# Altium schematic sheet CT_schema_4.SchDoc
size 282 x 169 mm
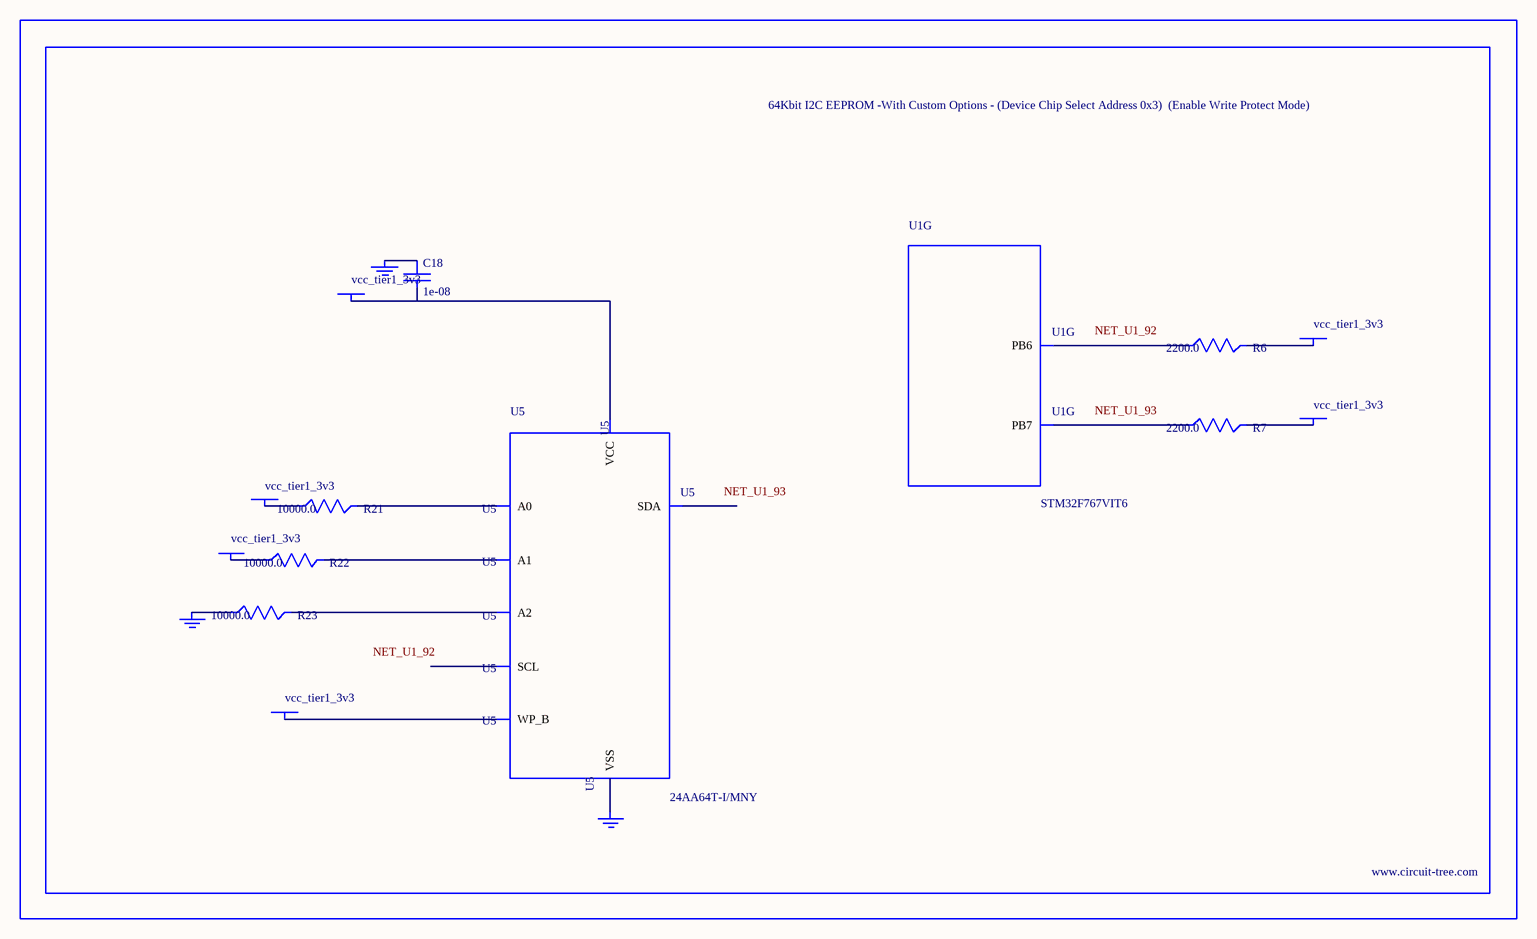
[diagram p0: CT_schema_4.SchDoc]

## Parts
BORDER3  (no value)
C18  1e-08  [C0402]
GND_INSTANCE_3_0  (no value)
GND_INSTANCE_3_1  (no value)
GND_INSTANCE_3_2  (no value)
POWER_INSTANCE_3_0  vcc_tier1_3v3
POWER_INSTANCE_3_1  vcc_tier1_3v3
POWER_INSTANCE_3_2  vcc_tier1_3v3
POWER_INSTANCE_3_3  vcc_tier1_3v3
POWER_INSTANCE_3_4  vcc_tier1_3v3
POWER_INSTANCE_3_5  vcc_tier1_3v3
R6  2200.0  [R0603]
R7  2200.0  [R0603]
R21  10000.0  [R0603]
R22  10000.0  [R0603]
R23  10000.0  [R0603]
U1  STM32F767VIT6  [LQFP100]  (part G of 11)
U5  24AA64T-I/MNY  [TDFN-8/6MM]

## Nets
NetC18_1: C18.1 GND_INSTANCE_3_1.0(GND)
NetC18_2: C18.2 POWER_INSTANCE_3_3.0(PWR) U5.8(VCC)
NetGND_INSTANCE_3_0_0: GND_INSTANCE_3_0.0(GND) R23.1
NetGND_INSTANCE_3_2_0: GND_INSTANCE_3_2.0(GND) U5.4(VSS)
NetPOWER_INSTANCE_3_0_0: POWER_INSTANCE_3_0.0(PWR) R21.1
NetPOWER_INSTANCE_3_1_0: POWER_INSTANCE_3_1.0(PWR) R22.1
NetPOWER_INSTANCE_3_2_0: POWER_INSTANCE_3_2.0(PWR) U5.7(WP_B)
NetPOWER_INSTANCE_3_4_0: POWER_INSTANCE_3_4.0(PWR) R6.2
NetPOWER_INSTANCE_3_5_0: POWER_INSTANCE_3_5.0(PWR) R7.2
NetR6_1: R6.1 U1.92(PB6)
NetR7_1: R7.1 U1.93(PB7)
NetR21_2: R21.2 U5.1(A0)
NetR22_2: R22.2 U5.2(A1)
NetR23_2: R23.2 U5.3(A2)

Not connected (* = marked no-connect by the designer): U5 5(SDA) 6(SCL)

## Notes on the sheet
- Labels drawn without touching a wire or pin: NET_U1_92, NET_U1_93

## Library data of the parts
BORDER3 = BORDER_PAGE3
C18 = C0402C103K3RAC
GND_INSTANCE_3_0-GND_INSTANCE_3_2 = GND
POWER_INSTANCE_3_0-POWER_INSTANCE_3_5 = PWR
R6 R7 = RC0603JR-072K2L
R21-R23 = RC0603JR-0710KL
